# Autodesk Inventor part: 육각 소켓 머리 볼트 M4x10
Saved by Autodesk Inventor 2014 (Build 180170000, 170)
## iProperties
Created: 2024-08
Part Number: 육각 소켓 머리 볼트 M4x10
Material: 일반
Document SubType Name: Modeling
Designer: dg
Density: 1 g/cm^3
Appearance: 기본값
Author: dg
Author: jhkim
Description: 6각머리 태핑 나사
Creation Date: 2024-08-09
Sending System: Autodesk Inventor 2025
Preprocessor: ST-DEVELOPER v20
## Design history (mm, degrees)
node "육각 소켓 머리 볼트 M4x101"
body "Solid1"
node "기준1"
